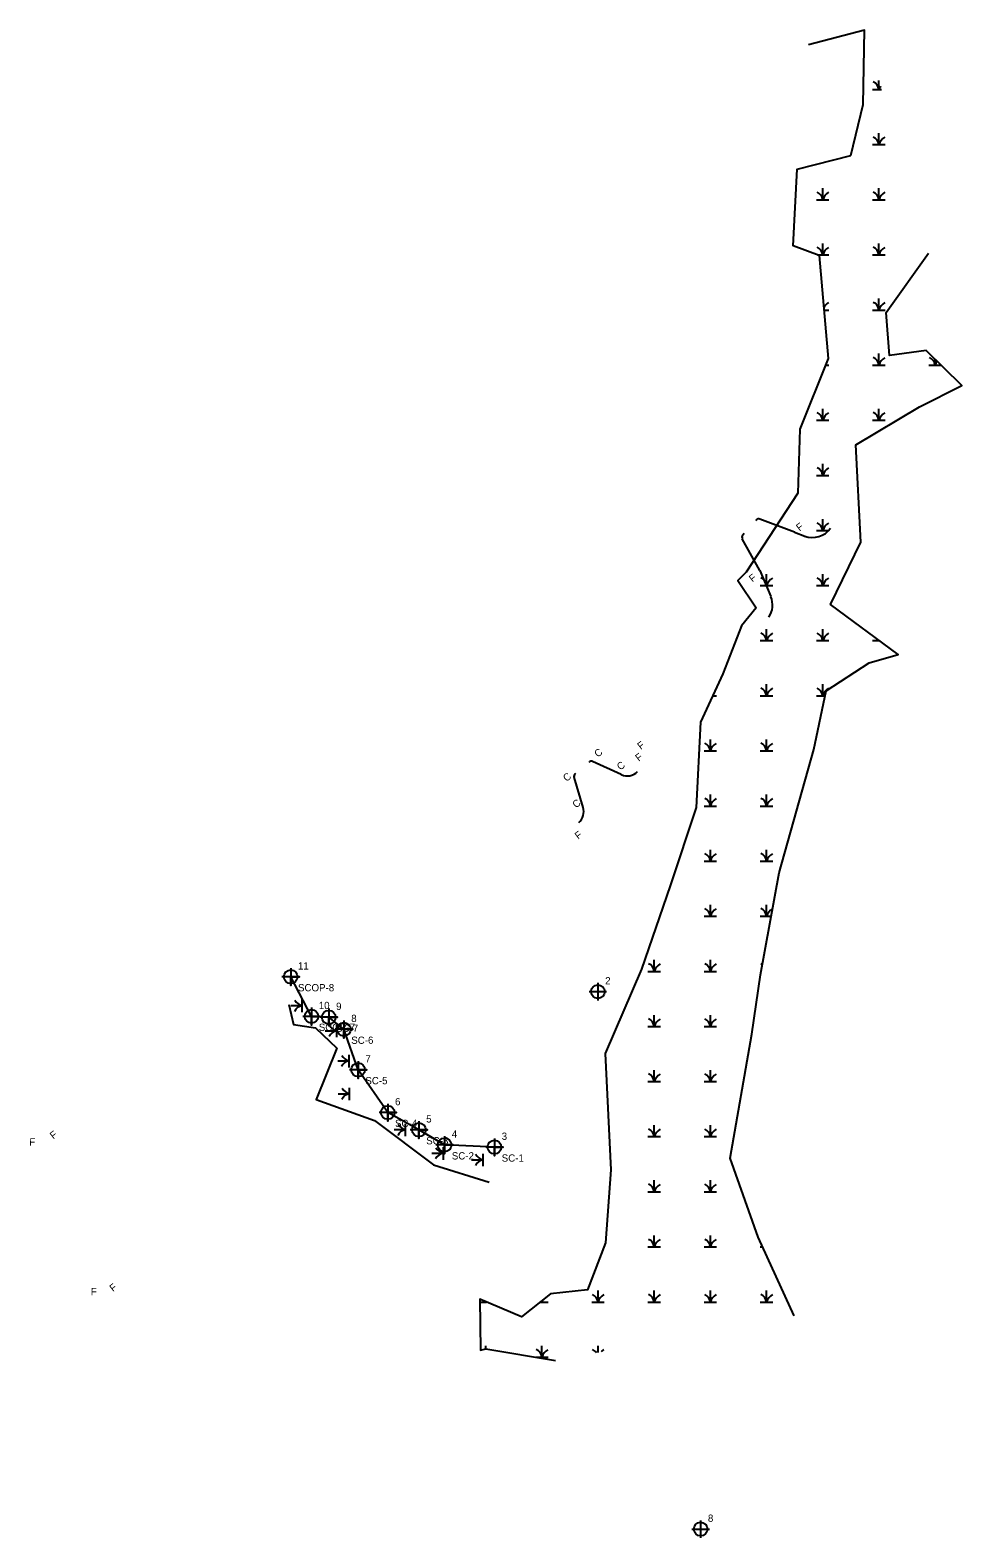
# Model space of a CAD drawing. Extents: x 2166958 to 2178986, y 64620 to 71122.
# Drawn here: x 2175174 to 2175814, y 65787 to 66824 of the extents above; entities that cross this region are included whole.
import ezdxf

# ---------------------------------------------------------------- set-up
doc = ezdxf.new("R2010")
doc.units = 0
for name, color, linetype in [('Default', 7, 'Continuous'), ('Old_Level_2', 7, 'Continuous'), ('Prop Horizontal Alignment', 7, 'Continuous'), ('Prop Horizontal Alignment Direction Label', 7, 'Continuous'), ('Prop Horizontal Alignment Station Label', 7, 'Continuous'), ('Prop Horizontal Alignment Tick Label', 7, 'Continuous'), ('Prop Horizontal Alignment Tick Large', 7, 'Continuous'), ('Prop Horizontal Alignment Tick Small', 7, 'Continuous'), ('Prop Rem of Exist Asph Pvmt', 7, 'Continuous')]:
    doc.layers.add(name, color=color, linetype=linetype)

# ---------------------------------------------------------------- blocks, each defined once
blk = doc.blocks.new('EXIST HYDRO SWAMP OR MARSH')
at = {"layer": 'Default'}
for p, q in [((0, -0.036), (0, 0.043)), ((0, 0), (0, 0)), ((-0.043, -0.036), (0.043, -0.036))]:
    blk.add_line(p, q, dxfattribs=at)
for centre, radius, start, end in [((-0.061, -0.04), 0.0615, 4.1403, 67.535), ((0.091, -0.066), 0.0961, 122.1274, 161.6222)]:
    blk.add_arc(centre, radius, start, end, dxfattribs=at)

msp = doc.modelspace()

# ---------------------------------------------------------------- linework, layer by layer
at = {"layer": 'Default'}
for p, q in [((2175672.4, 66486.6), (2175672.9, 66487.1)), ((2175699, 66478.7), (2175675, 66487.7)), ((2175675.1, 66452.3), (2175663, 66474.2)), ((2175664.3, 66477.7), (2175663.3, 66476.6)), ((2175699, 66478.7), (2175705.9, 66476)), ((2175675.1, 66452.3), (2175682.6, 66434.4)), ((2175557.7, 66320.5), (2175558, 66320.8)), ((2175579.9, 66312), (2175560.1, 66321)), ((2175553.7, 66289.5), (2175547.4, 66310.3)), ((2175548.5, 66312.8), (2175548, 66312.4))]:
    msp.add_line(p, q, dxfattribs=at)
for centre, radius, start, end in [((2175674.3, 66485.8), 2, 69.5048, 137.9152), ((2175664.8, 66475.2), 2, 137.7029, 208.6756), ((2175711.3, 66490), 15, 248.5623, 325.4647), ((2175668.8, 66428.5), 15, 326.3043, 22.8452), ((2175559.3, 66319.2), 2, 65.5061, 129.1335), ((2175549.3, 66310.9), 2, 128.9024, 196.9148), ((2175584, 66321.1), 10, 245.5061, 315.0401), ((2175544.1, 66286.6), 10, 310.6705, 16.9148)]:
    msp.add_arc(centre, radius, start, end, dxfattribs=at)
at = {"layer": 'Prop Horizontal Alignment'}
for points in [[(2175737.7, 66737.6), (2175746, 66772.7), (2175746.9, 66823.8), (2175708.5, 66813.8)], [(2175715.8, 66668.9), (2175698, 66675.6), (2175700.7, 66728.2), (2175737.7, 66737.6)], [(2175698.7, 65939.9), (2175673.9, 65994), (2175654.6, 66048.3), (2175669.5, 66133.5), (2175675.6, 66174.4), (2175688.3, 66244.4), (2175712.2, 66329.2), (2175720.6, 66369.6), (2175750.3, 66388.9), (2175770.2, 66394.5), (2175723.6, 66429), (2175744.4, 66471.8), (2175741.1, 66538.7), (2175784.8, 66564.9), (2175813.9, 66579.6), (2175789.4, 66603.5), (2175764.2, 66600.1), (2175761.8, 66629.6), (2175791, 66670.4)], [(2175715.8, 66668.9), (2175722, 66598.1), (2175702.5, 66549.6), (2175701.2, 66505.5), (2175665.6, 66451.2), (2175659.9, 66445.4), (2175672.6, 66426.7), (2175662.5, 66414.2), (2175649.6, 66381.2), (2175634.4, 66348.1), (2175631.4, 66289.4), (2175613.5, 66235.6), (2175593.8, 66178.2), (2175568.9, 66120.2), (2175572.8, 66040.3), (2175569.1, 65990.2), (2175556.7, 65957.9), (2175531.3, 65955), (2175511.3, 65939.2), (2175482.7, 65951.3), (2175483.2, 65916.2), (2175486.9, 65917.3), (2175534.6, 65909.3)], [(2175351.5, 66153.9), (2175354.6, 66140.2), (2175369.7, 66137.8), (2175384.5, 66124), (2175370.1, 66088.6), (2175410.2, 66074.3), (2175450.9, 66043.8), (2175489, 66031.8)]]:
    msp.add_lwpolyline(points, dxfattribs=at)
at = {"layer": 'Prop Horizontal Alignment Station Label'}
for p, q in [((2175756.9, 66783), (2175756.9, 66789.1)), ((2175752.6, 66783), (2175758.6, 66783)), ((2175756.9, 66745.1), (2175756.9, 66753)), ((2175752.6, 66745.1), (2175761.2, 66745.1)), ((2175718.3, 66707.2), (2175718.3, 66715.1)), ((2175756.9, 66707.2), (2175756.9, 66715.1)), ((2175714, 66707.2), (2175722.6, 66707.2)), ((2175752.6, 66707.2), (2175761.2, 66707.2)), ((2175718.3, 66669.3), (2175718.3, 66677.2)), ((2175756.9, 66669.3), (2175756.9, 66677.2)), ((2175714.7, 66669.3), (2175722.6, 66669.3)), ((2175752.6, 66669.3), (2175761.2, 66669.3)), ((2175756.9, 66631.4), (2175756.9, 66639.3)), ((2175719.1, 66631.4), (2175722.6, 66631.4)), ((2175752.6, 66631.4), (2175761.2, 66631.4)), ((2175756.9, 66593.5), (2175756.9, 66601.4)), ((2175795.5, 66593.5), (2175795.5, 66597.5)), ((2175720.2, 66593.5), (2175722.6, 66593.5)), ((2175752.6, 66593.5), (2175761.2, 66593.5)), ((2175791.2, 66593.5), (2175799.6, 66593.5)), ((2175718.3, 66555.6), (2175718.3, 66563.5)), ((2175756.9, 66555.6), (2175756.9, 66563.5)), ((2175714, 66555.6), (2175722.6, 66555.6)), ((2175752.6, 66555.6), (2175761.2, 66555.6)), ((2175718.3, 66517.7), (2175718.3, 66525.6)), ((2175714, 66517.7), (2175722.6, 66517.7)), ((2175718.3, 66479.9), (2175718.3, 66487.7)), ((2175714, 66479.9), (2175722.6, 66479.9)), ((2175675.4, 66442), (2175684, 66442)), ((2175679.7, 66442), (2175679.7, 66449.9)), ((2175714, 66442), (2175722.6, 66442)), ((2175718.3, 66442), (2175718.3, 66449.9)), ((2175679.7, 66404.1), (2175679.7, 66412)), ((2175718.3, 66404.1), (2175718.3, 66412)), ((2175675.4, 66404.1), (2175684, 66404.1)), ((2175714, 66404.1), (2175722.6, 66404.1)), ((2175752.6, 66404.1), (2175757.2, 66404.1)), ((2175756.9, 66404.1), (2175756.9, 66404.3)), ((2175679.7, 66366.2), (2175679.7, 66374.1)), ((2175718.3, 66366.2), (2175718.3, 66374.1)), ((2175642.7, 66366.2), (2175645.4, 66366.2)), ((2175675.4, 66366.2), (2175684, 66366.2)), ((2175714, 66366.2), (2175719.9, 66366.2)), ((2175636.8, 66328.3), (2175645.4, 66328.3)), ((2175641.1, 66328.3), (2175641.1, 66336.2)), ((2175675.4, 66328.3), (2175684, 66328.3)), ((2175679.7, 66328.3), (2175679.7, 66336.2)), ((2175641.1, 66290.4), (2175641.1, 66298.3)), ((2175679.7, 66290.4), (2175679.7, 66298.3)), ((2175636.8, 66290.4), (2175645.4, 66290.4)), ((2175675.4, 66290.4), (2175684, 66290.4)), ((2175641.1, 66252.5), (2175641.1, 66260.4)), ((2175679.7, 66252.5), (2175679.7, 66260.4)), ((2175636.8, 66252.5), (2175645.4, 66252.5)), ((2175675.4, 66252.5), (2175684, 66252.5)), ((2175606.3, 66214.6), (2175606.8, 66214.6)), ((2175636.8, 66214.6), (2175645.4, 66214.6)), ((2175641.1, 66214.6), (2175641.1, 66222.5)), ((2175675.4, 66214.6), (2175682.9, 66214.6)), ((2175679.7, 66214.6), (2175679.7, 66222.5)), ((2175602.5, 66176.7), (2175602.5, 66184.6)), ((2175641.1, 66176.7), (2175641.1, 66184.6)), ((2175598.2, 66176.7), (2175606.8, 66176.7)), ((2175636.8, 66176.7), (2175645.4, 66176.7)), ((2175675.4, 66176.7), (2175676, 66176.7)), ((2175602.5, 66138.8), (2175602.5, 66146.7)), ((2175641.1, 66138.8), (2175641.1, 66146.7)), ((2175598.2, 66138.8), (2175606.8, 66138.8)), ((2175636.8, 66138.8), (2175645.4, 66138.8)), ((2175598.2, 66101), (2175606.8, 66101)), ((2175602.5, 66101), (2175602.5, 66108.8)), ((2175636.8, 66101), (2175645.4, 66101)), ((2175641.1, 66101), (2175641.1, 66108.8)), ((2175602.5, 66063.1), (2175602.5, 66071)), ((2175641.1, 66063.1), (2175641.1, 66071)), ((2175598.2, 66063.1), (2175606.8, 66063.1)), ((2175636.8, 66063.1), (2175645.4, 66063.1)), ((2175602.5, 66025.2), (2175602.5, 66033.1)), ((2175641.1, 66025.2), (2175641.1, 66033.1)), ((2175598.2, 66025.2), (2175606.8, 66025.2)), ((2175636.8, 66025.2), (2175645.4, 66025.2)), ((2175568, 65987.3), (2175568.2, 65987.3)), ((2175598.2, 65987.3), (2175606.8, 65987.3)), ((2175602.5, 65987.3), (2175602.5, 65995.2)), ((2175636.8, 65987.3), (2175645.4, 65987.3)), ((2175641.1, 65987.3), (2175641.1, 65995.2)), ((2175675.4, 65987.3), (2175677, 65987.3)), ((2175563.9, 65949.4), (2175563.9, 65957.3)), ((2175602.5, 65949.4), (2175602.5, 65957.3)), ((2175641.1, 65949.4), (2175641.1, 65957.3)), ((2175679.7, 65949.4), (2175679.7, 65957.3)), ((2175482.7, 65949.4), (2175487.2, 65949.4)), ((2175486.7, 65949.4), (2175486.7, 65949.6)), ((2175524.2, 65949.4), (2175529.6, 65949.4)), ((2175525.3, 65949.4), (2175525.3, 65950.2)), ((2175559.6, 65949.4), (2175568.2, 65949.4)), ((2175598.2, 65949.4), (2175606.8, 65949.4)), ((2175636.8, 65949.4), (2175645.4, 65949.4)), ((2175675.4, 65949.4), (2175684, 65949.4)), ((2175486.7, 65917.2), (2175486.7, 65919.4)), ((2175525.3, 65911.5), (2175525.3, 65919.4)), ((2175563.9, 65914.7), (2175563.9, 65919.4)), ((2175521.3, 65911.5), (2175529.6, 65911.5))]:
    msp.add_line(p, q, dxfattribs=at)
for centre, radius, start, end in [((2175750.7, 66782.5), 6.15, 4.1403, 67.535), ((2175766, 66779.9), 9.61, 146.458, 161.6222), ((2175750.7, 66744.6), 6.15, 4.1403, 67.535), ((2175766, 66742.1), 9.61, 122.1274, 161.6222), ((2175712.1, 66706.8), 6.15, 4.1403, 67.535), ((2175727.4, 66704.2), 9.61, 122.1274, 161.6222), ((2175750.7, 66706.8), 6.15, 4.1403, 67.535), ((2175766, 66704.2), 9.61, 122.1274, 161.6222), ((2175712.1, 66668.9), 6.15, 4.1403, 67.535), ((2175727.4, 66666.3), 9.61, 122.1274, 161.6222), ((2175750.7, 66668.9), 6.15, 4.1403, 67.535), ((2175766, 66666.3), 9.61, 122.1274, 161.6222), ((2175727.4, 66628.4), 9.61, 122.1274, 151.442), ((2175750.7, 66631), 6.15, 4.1403, 67.535), ((2175766, 66628.4), 9.61, 122.1274, 161.6222), ((2175727.4, 66590.5), 9.61, 122.1274, 124.3911), ((2175750.7, 66593.1), 6.15, 4.1403, 67.535), ((2175766, 66590.5), 9.61, 122.1274, 161.6222), ((2175789.3, 66593.1), 6.15, 4.1403, 67.535), ((2175804.6, 66590.5), 9.61, 143.6575, 161.6222), ((2175712.1, 66555.2), 6.15, 4.1403, 67.535), ((2175727.4, 66552.6), 9.61, 122.1274, 161.6222), ((2175750.7, 66555.2), 6.15, 4.1403, 67.535), ((2175766, 66552.6), 9.61, 122.1274, 161.6222), ((2175712.1, 66517.3), 6.15, 4.1403, 67.535), ((2175727.4, 66514.7), 9.61, 122.1274, 161.6222), ((2175712.1, 66479.4), 6.15, 4.1403, 67.535), ((2175727.4, 66476.8), 9.61, 122.1274, 161.6222), ((2175673.5, 66441.5), 6.15, 4.1403, 67.535), ((2175688.8, 66438.9), 9.61, 122.1274, 161.6222), ((2175712.1, 66441.5), 6.15, 4.1403, 67.535), ((2175727.4, 66438.9), 9.61, 122.1274, 161.6222), ((2175673.5, 66403.6), 6.15, 4.1403, 67.535), ((2175688.8, 66401), 9.61, 122.1274, 161.6222), ((2175712.1, 66403.6), 6.15, 4.1403, 67.535), ((2175727.4, 66401), 9.61, 122.1274, 161.6222), ((2175750.7, 66403.6), 6.15, 4.1403, 6.8863), ((2175766, 66401), 9.61, 160.2548, 161.6222), ((2175650.2, 66363.2), 9.61, 122.1274, 122.1381), ((2175673.5, 66365.7), 6.15, 4.1403, 67.535), ((2175688.8, 66363.2), 9.61, 122.1274, 161.6222), ((2175712.1, 66365.7), 6.15, 4.1403, 67.535), ((2175727.4, 66363.2), 9.61, 122.1274, 161.6222), ((2175634.9, 66327.9), 6.15, 4.1403, 67.535), ((2175650.2, 66325.3), 9.61, 122.1274, 161.6222), ((2175673.5, 66327.9), 6.15, 4.1403, 67.535), ((2175688.8, 66325.3), 9.61, 122.1274, 161.6222), ((2175634.9, 66290), 6.15, 4.1403, 67.535), ((2175650.2, 66287.4), 9.61, 122.1274, 161.6222), ((2175673.5, 66290), 6.15, 4.1403, 67.535), ((2175688.8, 66287.4), 9.61, 122.1274, 161.6222), ((2175634.9, 66252.1), 6.15, 4.1403, 67.535), ((2175650.2, 66249.5), 9.61, 122.1274, 161.6222), ((2175673.5, 66252.1), 6.15, 4.1403, 67.535), ((2175688.8, 66249.5), 9.61, 122.1274, 161.6222), ((2175634.9, 66214.2), 6.15, 4.1403, 67.535), ((2175650.2, 66211.6), 9.61, 122.1274, 161.6222), ((2175673.5, 66214.2), 6.15, 4.1403, 67.535), ((2175688.8, 66211.6), 9.61, 122.1274, 161.6222), ((2175596.3, 66176.3), 6.15, 4.1403, 67.535), ((2175611.6, 66173.7), 9.61, 122.1274, 161.6222), ((2175634.9, 66176.3), 6.15, 4.1403, 67.535), ((2175650.2, 66173.7), 9.61, 122.1274, 161.6222), ((2175673.5, 66176.3), 6.15, 57.2087, 67.535), ((2175596.3, 66138.4), 6.15, 4.1403, 67.535), ((2175611.6, 66135.8), 9.61, 122.1274, 161.6222), ((2175634.9, 66138.4), 6.15, 4.1403, 67.535), ((2175650.2, 66135.8), 9.61, 122.1274, 161.6222), ((2175596.3, 66100.5), 6.15, 4.1403, 67.535), ((2175611.6, 66097.9), 9.61, 122.1274, 161.6222), ((2175634.9, 66100.5), 6.15, 4.1403, 67.535), ((2175650.2, 66097.9), 9.61, 122.1274, 161.6222), ((2175596.3, 66062.6), 6.15, 4.1403, 67.535), ((2175611.6, 66060), 9.61, 122.1274, 161.6222), ((2175634.9, 66062.6), 6.15, 4.1403, 67.535), ((2175650.2, 66060), 9.61, 122.1274, 161.6222), ((2175596.3, 66024.7), 6.15, 4.1403, 67.535), ((2175611.6, 66022.1), 9.61, 122.1274, 161.6222), ((2175634.9, 66024.7), 6.15, 4.1403, 67.535), ((2175650.2, 66022.1), 9.61, 122.1274, 161.6222), ((2175596.3, 65986.8), 6.15, 4.1403, 67.535), ((2175611.6, 65984.3), 9.61, 122.1274, 161.6222), ((2175634.9, 65986.8), 6.15, 4.1403, 67.535), ((2175650.2, 65984.3), 9.61, 122.1274, 161.6222), ((2175557.7, 65948.9), 6.15, 4.1403, 67.535), ((2175596.3, 65948.9), 6.15, 4.1403, 67.535), ((2175634.9, 65948.9), 6.15, 4.1403, 67.535), ((2175673.5, 65948.9), 6.15, 4.1403, 67.535), ((2175480.5, 65948.9), 6.15, 4.1403, 6.2283), ((2175495.8, 65946.4), 9.61, 160.4413, 161.6222), ((2175519.1, 65948.9), 6.15, 4.1403, 11.4065), ((2175534.4, 65946.4), 9.61, 153.3747, 161.6222), ((2175573, 65946.4), 9.61, 122.1274, 161.6222), ((2175611.6, 65946.4), 9.61, 122.1274, 161.6222), ((2175650.2, 65946.4), 9.61, 122.1274, 161.6222), ((2175688.8, 65946.4), 9.61, 122.1274, 161.6222), ((2175480.5, 65911.1), 6.15, 59.738, 64.4233), ((2175519.1, 65911.1), 6.15, 4.1403, 67.535), ((2175534.4, 65908.5), 9.61, 122.1274, 161.6222), ((2175557.7, 65911.1), 6.15, 34.5149, 67.535), ((2175573, 65908.5), 9.61, 122.1274, 135.9425)]:
    msp.add_arc(centre, radius, start, end, dxfattribs=at)
at = {"layer": 'Prop Horizontal Alignment Tick Label'}
msp.add_lwpolyline([(2175492.7, 66055.9), (2175458.4, 66057.4), (2175440.8, 66067.8), (2175419.4, 66079.7), (2175399, 66109.1), (2175389.3, 66136.9), (2175378.9, 66145.2), (2175367, 66145.8), (2175352.7, 66173)], dxfattribs=at)
at = {"layer": 'Prop Horizontal Alignment Tick Large'}
for points in [[(2175352.7, 66179), (2175352.7, 66167), (2175352.7, 66173), (2175358.7, 66173), (2175346.7, 66173)], [(2175367, 66151.8), (2175367, 66139.8), (2175367, 66145.8), (2175373, 66145.8), (2175361, 66145.8)], [(2175378.9, 66151.2), (2175378.9, 66139.2), (2175378.9, 66145.2), (2175384.9, 66145.2), (2175372.9, 66145.2)], [(2175389.3, 66142.9), (2175389.3, 66130.9), (2175389.3, 66136.9), (2175395.3, 66136.9), (2175383.3, 66136.9)], [(2175399, 66115.1), (2175399, 66103.1), (2175399, 66109.1), (2175405, 66109.1), (2175393, 66109.1)], [(2175419.4, 66085.7), (2175419.4, 66073.7), (2175419.4, 66079.7), (2175425.4, 66079.7), (2175413.4, 66079.7)], [(2175440.8, 66073.8), (2175440.8, 66061.8), (2175440.8, 66067.8), (2175446.8, 66067.8), (2175434.8, 66067.8)], [(2175458.4, 66063.4), (2175458.4, 66051.4), (2175458.4, 66057.4), (2175464.4, 66057.4), (2175452.4, 66057.4)], [(2175492.7, 66061.9), (2175492.7, 66049.9), (2175492.7, 66055.9), (2175498.7, 66055.9), (2175486.7, 66055.9)]]:
    msp.add_lwpolyline(points, dxfattribs=at)
for centre in [(2175352.7, 66173), (2175367, 66145.8), (2175378.9, 66145.2), (2175389.3, 66136.9), (2175399, 66109.1), (2175419.4, 66079.7), (2175440.8, 66067.8), (2175458.4, 66057.4), (2175492.7, 66055.9)]:
    msp.add_circle(centre, 4.69, dxfattribs=at)
at = {"layer": 'Prop Rem of Exist Asph Pvmt'}
for points in [[(2175557.8, 66162.8), (2175563.8, 66162.8)], [(2175563.8, 66168.8), (2175563.8, 66162.8)], [(2175563.8, 66162.8), (2175569.8, 66162.8)], [(2175563.8, 66162.8), (2175563.8, 66156.8)], [(2175634.4, 65799.3), (2175634.4, 65793.3)], [(2175628.4, 65793.3), (2175634.4, 65793.3)], [(2175634.4, 65793.3), (2175640.4, 65793.3)], [(2175634.4, 65793.3), (2175634.4, 65787.3)]]:
    msp.add_lwpolyline(points, dxfattribs=at)
for centre in [(2175563.8, 66162.8), (2175634.4, 65793.3)]:
    msp.add_circle(centre, 4.69, dxfattribs=at)

# ---------------------------------------------------------------- block references
at = {"layer": 'Prop Horizontal Alignment Station Label', "xscale": 99.99980000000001, "yscale": 99.99980000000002, "rotation": 90}
for p in [(2175357, 66153), (2175380.8, 66135.7), (2175389.3, 66115), (2175389.6, 66092.4), (2175428.1, 66067.7), (2175454, 66051.5), (2175481.3, 66047)]:
    msp.add_blockref('EXIST HYDRO SWAMP OR MARSH', p, dxfattribs=at)

# ---------------------------------------------------------------- texts
at = {"layer": 'Default'}
for s, rotation, p in [('F', 37.8096, (2175702.4, 66479.1)), ('F', 37.8096, (2175670, 66444)), ('C', 37.8415, (2175563.7, 66323.6)), ('F', 37.8096, (2175593.3, 66328.9)), ('C', 37.8415, (2175579.2, 66314.7)), ('F', 37.8096, (2175591.9, 66320.8)), ('C', 37.8415, (2175542.2, 66306.9)), ('C', 37.8415, (2175548.7, 66288.7)), ('F', 37.8096, (2175550.3, 66267.2)), ('F', 359.3743, (2175173.1, 66057)), ('F', 37.8096, (2175189.6, 66061.1)), ('F', 359.3743, (2175215.3, 65954.1)), ('F', 37.8096, (2175230.6, 65956.2))]:
    msp.add_text(s, height=5, rotation=rotation, dxfattribs=at).set_placement(p)
at = {"layer": 'Old_Level_2'}
for s, p in [('2', (2175568.8, 66167.8)), ('8', (2175639.4, 65798.3))]:
    msp.add_text(s, height=5, dxfattribs=at).set_placement(p)
at = {"layer": 'Prop Horizontal Alignment Direction Label'}
for s, p in [('SCOP-8', (2175357.7, 66163)), ('SCOP-7', (2175372, 66135.8)), ('SC-7', (2175383.9, 66135.2)), ('SC-6', (2175394.3, 66126.9)), ('SC-5', (2175404, 66099.1)), ('SC-4', (2175424.4, 66069.7)), ('SC-3', (2175445.8, 66057.8)), ('SC-2', (2175463.4, 66047.4)), ('SC-1', (2175497.7, 66045.9))]:
    msp.add_text(s, height=5, dxfattribs=at).set_placement(p)
at = {"layer": 'Prop Horizontal Alignment Tick Small'}
for s, p in [('11', (2175357.7, 66178)), ('10', (2175372, 66150.8)), ('9', (2175383.9, 66150.2)), ('8', (2175394.3, 66141.9)), ('7', (2175404, 66114.1)), ('6', (2175424.4, 66084.7)), ('5', (2175445.8, 66072.8)), ('4', (2175463.4, 66062.4)), ('3', (2175497.7, 66060.9))]:
    msp.add_text(s, height=5, dxfattribs=at).set_placement(p)

doc.saveas('drawing.dxf')
